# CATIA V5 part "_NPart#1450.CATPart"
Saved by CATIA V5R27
Part number: Connector^Endstop_Opto_TCST2103_D‚faut
Revision: ANY
Definition: UNKNOWN
Nomenclature: Connector^Endstop_Opto_TCST2103_D‚faut
Source: Unknown
Bounding box of the stored display mesh (mm): x 15.04 to 20.75, y -5 to 5, z -1.66 to 7
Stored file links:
  E:\university\my-thesis\My Thesis Publication\Final-Updata\CAD\_NPart#1450.CATPart
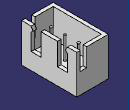
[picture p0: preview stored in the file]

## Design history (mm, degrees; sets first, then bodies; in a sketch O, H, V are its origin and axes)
Body1 "Boss.-Extru.2" (main body)
  Solid1: solid without history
